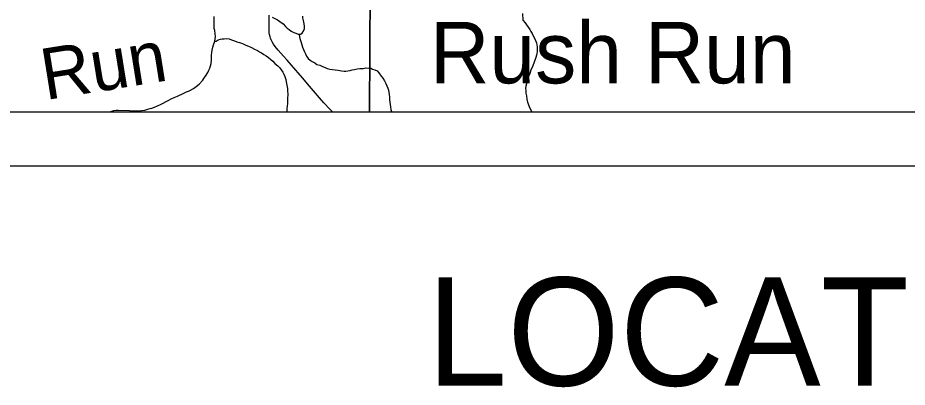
# Model space of a CAD drawing. Extents: x -8.8 to 41.4, y 0 to 34.6.
# Drawn here: x 3.671 to 5.315, y 13.591 to 14.274 of the extents above; entities that cross this region are included whole.
import ezdxf

# ---------------------------------------------------------------- set-up
doc = ezdxf.new("R2010")
doc.units = 0
for name, color, linetype in [('GM_X_Corporation', 7, 'Continuous'), ('GM_X_County_Road', 7, 'Continuous'), ('GM_X_Minor_River', 7, 'Continuous'), ('GM_X_Minor_River_Text', 7, 'Continuous'), ('GM_X_Unincorporated_Text', 7, 'Continuous'), ('SH_Border', 7, 'Continuous'), ('SH_Data', 7, 'Continuous')]:
    doc.layers.add(name, color=color, linetype=linetype)

msp = doc.modelspace()

# ---------------------------------------------------------------- linework, layer by layer
at = {"layer": 'GM_X_Corporation'}
msp.add_lwpolyline([(2.1, 18.6925), (2.1, 14.1), (5.3301, 14.1)], dxfattribs=at)
for points in [[(3.3248, 14.1), (4.3207, 14.1), (4.3237, 14.5538), (3.3268, 14.5649)], [(4.3207, 14.1), (5.3314, 14.1), (5.3342, 14.4488), (5.3337, 14.5401), (4.3237, 14.5538)]]:
    msp.add_lwpolyline(points, close=True, dxfattribs=at)
at = {"layer": 'GM_X_County_Road'}
msp.add_lwpolyline([(4.2523, 14.1), (4.2475, 14.1048), (4.2365, 14.1166), (4.2283, 14.1259), (4.2098, 14.1477), (4.1969, 14.1628), (4.1767, 14.1864), (4.1685, 14.1957), (4.1619, 14.2031), (4.1524, 14.2139), (4.1468, 14.2206), (4.1436, 14.2253), (4.141, 14.2295), (4.1394, 14.2328), (4.138, 14.2364), (4.1373, 14.2388), (4.1363, 14.2427), (4.1356, 14.2462), (4.1353, 14.2516), (4.1352, 14.2568), (4.1353, 14.2631), (4.1358, 14.2784)], dxfattribs=at)
at = {"layer": 'GM_X_Minor_River'}
for points in [[(4.0358, 14.2443), (4.0348, 14.25), (4.0341, 14.2542), (4.0339, 14.2592), (4.0341, 14.2649), (4.0338, 14.2706), (4.0336, 14.2759)], [(4.141, 14.2748), (4.1507, 14.27), (4.1555, 14.2672), (4.1611, 14.2624), (4.1655, 14.2578), (4.1688, 14.2546), (4.1722, 14.2519), (4.1763, 14.2491), (4.1808, 14.2467), (4.1845, 14.2454), (4.189, 14.2438), (4.1932, 14.2437), (4.1967, 14.2455), (4.1998, 14.25), (4.2007, 14.2537), (4.2008, 14.2583), (4.2002, 14.2629), (4.1992, 14.2686), (4.1978, 14.2736), (4.1976, 14.277)], [(4.6041, 14.2815), (4.6045, 14.2693), (4.6085, 14.2647), (4.6114, 14.2608), (4.6143, 14.2565), (4.6173, 14.2523), (4.6194, 14.2484), (4.622, 14.2445), (4.6238, 14.2407), (4.6263, 14.236), (4.6281, 14.2318), (4.6295, 14.2276), (4.6305, 14.2238), (4.6311, 14.2199), (4.6309, 14.2112), (4.6304, 14.2078), (4.6296, 14.2044), (4.6283, 14.2003), (4.6274, 14.1969), (4.6258, 14.1935), (4.6221, 14.1833), (4.6201, 14.1788), (4.6185, 14.1751), (4.6172, 14.1709), (4.6152, 14.1653), (4.6135, 14.1612), (4.6119, 14.1574), (4.611, 14.1517), (4.6101, 14.1476), (4.6096, 14.143), (4.6099, 14.1396), (4.6101, 14.1346), (4.6111, 14.1293), (4.6121, 14.1236), (4.6134, 14.1178), (4.6159, 14.1098), (4.6202, 14.1005), (4.6208, 14.1)], [(3.8407, 14.1), (3.8412, 14.1001), (3.8446, 14.1011), (3.8481, 14.1022), (3.8527, 14.1028), (3.8561, 14.1031), (3.8773, 14.1025), (3.8807, 14.102), (3.8868, 14.1018), (3.8997, 14.1022), (3.9058, 14.1028), (3.9111, 14.1046), (3.9153, 14.106), (3.9188, 14.107), (3.9234, 14.1088), (3.9288, 14.1109), (3.9349, 14.1134), (3.9395, 14.1159), (3.9449, 14.1192), (3.9499, 14.1217), (3.9546, 14.1239), (3.9596, 14.1264), (3.9661, 14.1292), (3.9696, 14.131), (3.9742, 14.1328), (3.9826, 14.1368), (3.9861, 14.1382), (3.9899, 14.14), (3.9957, 14.1432), (4.0007, 14.1465), (4.0058, 14.1509), (4.0128, 14.1583), (4.0148, 14.1617), (4.0188, 14.1677), (4.0223, 14.1725), (4.024, 14.177), (4.026, 14.1808), (4.0285, 14.189), (4.0287, 14.1963), (4.0288, 14.2004), (4.0289, 14.2046), (4.0295, 14.2095), (4.03, 14.2141), (4.0313, 14.2194), (4.0325, 14.2239), (4.035, 14.2307), (4.0359, 14.2348), (4.036, 14.239), (4.0358, 14.2443)], [(4.1909, 14.2422), (4.1922, 14.2354), (4.1932, 14.2319), (4.1947, 14.2281), (4.196, 14.2235), (4.1974, 14.2196), (4.1988, 14.215), (4.201, 14.2108), (4.2024, 14.2073), (4.2046, 14.2031), (4.2079, 14.1988), (4.2116, 14.1957), (4.2153, 14.1929), (4.2198, 14.1905), (4.2235, 14.1877), (4.2291, 14.186), (4.234, 14.1836), (4.2389, 14.1816), (4.243, 14.1803), (4.2479, 14.1791), (4.2524, 14.1782), (4.2573, 14.1773), (4.263, 14.1767), (4.2691, 14.1758), (4.274, 14.1753), (4.2774, 14.1752), (4.2808, 14.1755), (4.285, 14.1761), (4.2892, 14.1775), (4.2934, 14.1785), (4.298, 14.1792), (4.3029, 14.1798), (4.3067, 14.1801), (4.3102, 14.1803), (4.3144, 14.181), (4.3197, 14.1808), (4.3234, 14.1804), (4.3268, 14.1791), (4.3309, 14.1775), (4.3351, 14.1755), (4.3384, 14.1719), (4.3428, 14.1661), (4.3457, 14.1619), (4.3486, 14.1572), (4.3511, 14.1526), (4.3529, 14.148), (4.3547, 14.1438), (4.3561, 14.1403), (4.3574, 14.1319), (4.358, 14.1273), (4.3582, 14.1224), (4.3585, 14.1178), (4.3591, 14.1136), (4.3597, 14.109), (4.3607, 14.1041), (4.3614, 14.1006), (4.3615, 14.1)], [(4.035, 14.2307), (4.0376, 14.2306), (4.0415, 14.2328), (4.0453, 14.2342), (4.0488, 14.2348), (4.0526, 14.2351), (4.0571, 14.2354), (4.0617, 14.2349), (4.0658, 14.2332), (4.0711, 14.2315), (4.0759, 14.2295), (4.0804, 14.2279), (4.0842, 14.2266), (4.0876, 14.2254), (4.0921, 14.2234), (4.0973, 14.2213), (4.1029, 14.2189), (4.1086, 14.216), (4.1138, 14.2132), (4.1175, 14.2109), (4.1213, 14.2089), (4.1257, 14.2061), (4.1298, 14.2033), (4.1343, 14.2001), (4.1387, 14.1966), (4.1421, 14.1938), (4.1461, 14.1895), (4.1513, 14.1852), (4.155, 14.1813), (4.1579, 14.1774), (4.1605, 14.1735), (4.1626, 14.1693), (4.1644, 14.1651), (4.1662, 14.1597), (4.1668, 14.1551), (4.1681, 14.149), (4.1691, 14.1429), (4.1697, 14.1379), (4.17, 14.1334), (4.1697, 14.1235), (4.1692, 14.1201), (4.1691, 14.1159), (4.1685, 14.1099), (4.1684, 14.1061), (4.1683, 14.1019), (4.1686, 14.1)]]:
    msp.add_lwpolyline(points, dxfattribs=at)
at = {"layer": 'SH_Border'}
for p, q in [((2.1, 14.1), (8.9, 14.1)), ((2, 14), (9, 14))]:
    msp.add_line(p, q, dxfattribs=at)

# ---------------------------------------------------------------- texts
at = {"layer": 'GM_X_Minor_River_Text'}
msp.add_text('Run', height=0.09469, rotation=9.1343, dxfattribs=at).set_placement((3.7217, 14.1215))
at = {"layer": 'GM_X_Unincorporated_Text'}
msp.add_text('Rush Run', height=0.11363, rotation=359.9986, dxfattribs=at).set_placement((4.433, 14.1526))
at = {"layer": 'SH_Data'}
msp.add_text('LOCATION MAP', height=0.2, dxfattribs=at).set_placement((4.4269, 13.5937))

doc.saveas('drawing.dxf')
